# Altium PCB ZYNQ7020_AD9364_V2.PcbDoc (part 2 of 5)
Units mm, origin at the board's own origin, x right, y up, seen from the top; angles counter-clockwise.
Board outline 88.95 x 91.52 mm, 4 copper layers (Top Layer, Layer 1, Layer 2, Bottom Layer), stack 0.603 mm thick; 285 components, 278 nets, 1497 pads, 1247 vias.
Unrouted connection lines stored in the file: 367.
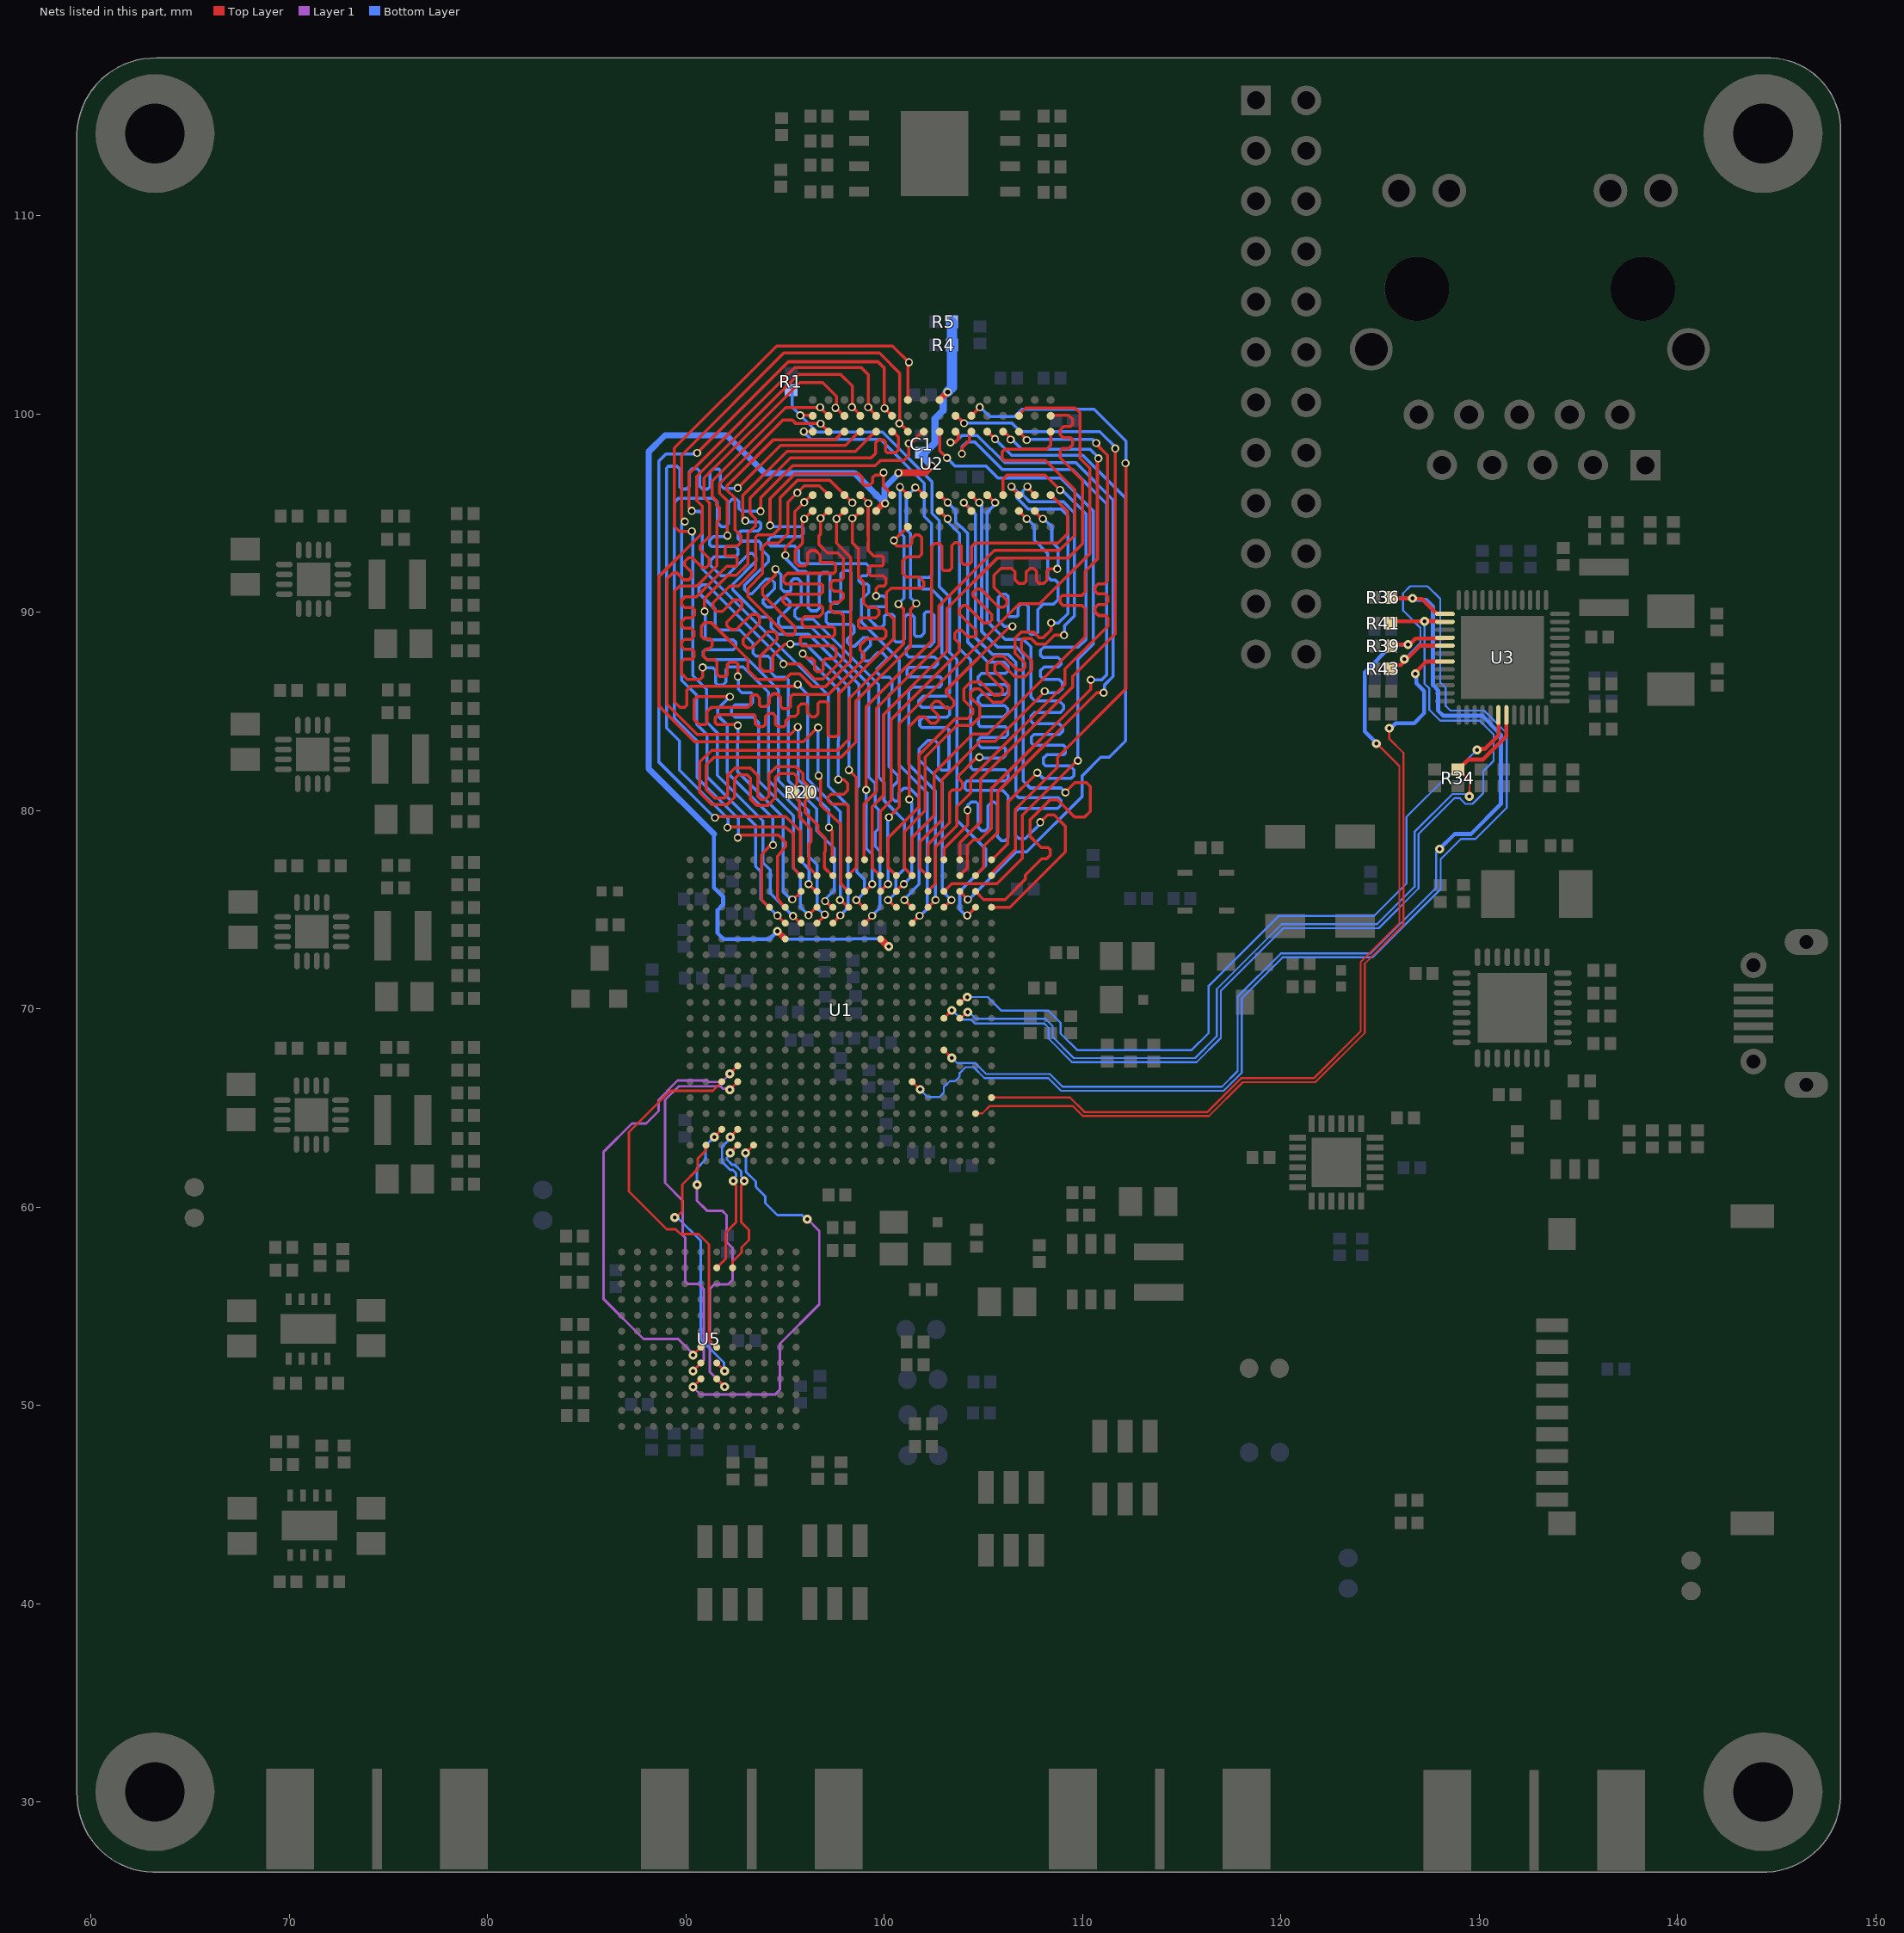
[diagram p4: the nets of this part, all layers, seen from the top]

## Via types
v1: diameter 0.45, hole 0.2, Top Layer to Bottom Layer, tented both sides, 995 vias
v2: diameter 0.406, hole 0.254, Top Layer to Bottom Layer, tented both sides, 118 vias
v3: diameter 1, hole 0.5, Top Layer to Bottom Layer, 116 vias
v4: diameter 0.5, hole 0.3, Top Layer to Bottom Layer, tented both sides, 16 vias
v5: diameter 0.406, hole 0.254, Top Layer to Bottom Layer, 2 vias

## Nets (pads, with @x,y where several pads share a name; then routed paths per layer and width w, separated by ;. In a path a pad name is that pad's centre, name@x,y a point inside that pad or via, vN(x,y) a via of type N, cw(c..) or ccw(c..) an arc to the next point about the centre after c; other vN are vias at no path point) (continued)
CTRL_OUT4: U1.U14 U5.F6 | length 22.7
  Top Layer w0.127: v1(90.354,52.536) U5.F6@90.754,52.934 ; v1@92.217,66.723 U1.U14@92.61,67.116
  Layer 1 w0.102: 91.053,66.389 91.135,66.307 91.805,66.307 v1(92.217,66.718)
  Layer 1 w0.127: v1(90.354,52.536) 90.354,52.597 89.611,53.34 87.859,53.34 85.852,55.347 85.852,62.789 87.274,64.211 87.986,64.211 88.621,64.846 88.621,65.405 89.052,65.837 89.052,65.862 89.579,66.389 91.053,66.389
CTRL_OUT5: U1.U15 U5.F5 | length 19.8
  Top Layer w0.127: v1(90.354,51.734) U5.F5@90.754,52.134 ; v1@92.217,65.923 U1.U15@92.61,66.316
  Layer 1 w0.127: v1(90.354,51.734) 90.907,52.287 90.907,55.855 90.637,56.124 90.053,56.124 89.967,56.21 89.967,58.455 89.842,58.58 89.842,60.323 88.951,61.214 88.951,65.405 89.637,66.091 91.749,66.091 91.876,65.964 92.171,65.964 v1(92.217,65.918)
CTRL_OUT6: U1.T19 U5.F4 | length 21
  Top Layer w0.127: v1(90.354,50.918) 90.354,50.934 U5.F4@90.754,51.334 ; v1(93.006,62.732) 93.013,62.732 93.411,63.129 U1.T19@93.423,63.129
  Layer 1 w0.127: v1(90.354,50.918) v1@90.358,50.914 ; v1@90.358,50.957 v1@90.358,50.914 ; v1(96.123,59.394) 96.723,58.794 96.723,55.093 94.742,53.111 94.742,52.682 94.744,52.68 94.744,50.794 94.489,50.539 93.996,50.539 93.991,50.544 90.728,50.544 v1@90.358,50.914
  Bottom Layer w0.127: v1(90.354,50.918) v1@90.411,50.861 ; v1(93.006,62.732) 93.03,62.707 93.03,61.776 93.521,61.285 93.521,61.02 93.599,60.942 93.599,60.935 93.998,60.535 93.998,60.205 94.615,59.588 95.86,59.588 96.054,59.394 v1(96.123,59.394)
CTRL_OUT7: U1.V18 U5.G4 | length 16.2
  Top Layer w0.127: v1@91.43,63.536 U1.V18@91.823,63.929 ; U5.G4@91.554,51.334 v1(91.954,50.934)
  Layer 1 w0.127: v1@90.553,60.898 90.553,60.323 91.059,59.817 91.821,59.817 92.05,59.588 92.05,58.235 92.344,57.94 92.344,56.32 92.133,56.109 91.44,56.109 91.211,55.88 91.211,51.677 v1(91.954,50.934)
  Bottom Layer w0.127: v1(90.56,61.122) 90.56,61.96 90.991,62.39 90.991,63.092 v1(91.43,63.532)
DATA_CLK_N: U1.U19 U5.H11 | length 7.4
  Top Layer w0.127: v1@92.23,62.736 U1.U19@92.623,63.129 ; U5.H11@92.354,56.934 92.354,57.249 92.811,57.706 92.811,57.965 93.176,58.33 93.176,58.843 92.786,59.233 92.786,61.08 92.939,61.232 v1(92.939,61.316)
  Bottom Layer w0.127: v1(92.23,62.732) 92.23,62.652 92.074,62.496 92.074,62.39 92.342,62.122 92.475,62.122 92.786,61.811 92.786,61.551 92.939,61.399 v1(92.939,61.316)
DATA_CLK_P: U1.U18 U5.G11 | length 8.2
  Top Layer w0.127: U5.G11@91.554,56.934 92.011,57.391 92.011,58.712 92.532,59.233 92.532,61.08 92.38,61.232 v1(92.38,61.316) ; v1@92.23,63.536 U1.U18@92.623,63.929
  Bottom Layer w0.127: v1(92.23,63.532) 92.23,63.454 91.82,63.044 91.82,62.285 92.237,61.868 92.369,61.868 92.532,61.706 92.532,61.551 92.38,61.399 v1(92.38,61.316)
DDR3_A0: U1.N2 U2.N3 | length 40.5
  Top Layer w0.152: v2(92.093,79.142) 92.118,79.167 95.018,79.167 95.418,78.833 95.418,77.106 U1.N2@95.771,76.719 ; v2(92.615,96.266) 94.765,98.416 98.04,98.416 98.79,99.166 U2.N3@98.74,99.166
  Bottom Layer w0.152: v2@92.118,79.217 92.118,79.592 89.668,82.042 89.668,83.513 89.015,84.166 89.015,97.266 89.115,97.366 89.54,97.366 89.69,97.216 89.69,96.316 89.79,96.216 90.015,96.216 90.165,96.366 90.165,97.091 90.315,97.241 90.565,97.241 90.69,97.116 90.69,96.366 90.84,96.216 91.09,96.216 91.215,96.341 91.215,97.091 91.34,97.216 91.665,97.216 91.74,97.141 91.74,96.416 91.915,96.241 v2@92.565,96.241
DDR3_A1: U1.K2 U2.P7 | length 39.7
  Top Layer w0.152: v2(95.265,88.401) 94.99,88.401 94.39,87.801 94.39,87.101 94.315,87.026 93.915,87.026 93.74,87.201 93.74,87.776 94.59,88.626 94.59,88.876 94.44,89.026 94.14,89.026 93.315,88.201 93.09,88.201 92.89,88.401 92.89,88.626 93.715,89.451 93.715,89.751 93.565,89.901 93.315,89.901 92.54,89.126 92.265,89.126 92.065,89.326 92.065,89.501 92.815,90.251 92.815,90.501 92.69,90.626 92.415,90.626 91.84,90.051 91.54,90.051 91.365,90.226 91.365,90.476 92.215,91.326 92.64,91.326 93.515,92.201 93.515,93.801 93.615,93.901 94.39,93.901 94.74,94.251 94.74,95.776 95.615,96.651 97.265,96.651 v2(98.39,95.526) ; U1.K2@98.182,76.719 98.593,77.129 98.593,81.667 v2(98.218,82.042)
  Bottom Layer w0.152: v2(95.265,88.401) 96.04,88.401 98.215,86.226 98.215,84.67 98.218,84.667 v2(98.218,82.042) ; v2(98.39,95.526) v2@98.39,95.551
DDR3_A2: U1.M3 U2.P3 | length 40.6
  Top Layer w0.152: v2@90.84,87.241 90.84,86.741 90.715,86.616 90.065,86.616 89.79,86.891 89.79,87.516 89.915,87.641 90.315,87.641 90.415,87.741 90.415,88.016 90.29,88.141 89.915,88.141 89.79,88.266 89.79,88.516 89.915,88.641 90.265,88.641 90.415,88.791 90.415,89.041 90.265,89.191 89.915,89.191 89.79,89.316 89.79,89.541 89.965,89.716 90.29,89.716 90.44,89.866 90.44,90.116 90.315,90.241 89.94,90.241 89.79,90.391 89.79,90.616 89.965,90.791 90.54,90.791 92.065,92.316 92.515,92.316 92.59,92.391 92.59,92.716 92.465,92.841 92.04,92.841 91.965,92.916 91.965,93.241 92.065,93.341 92.59,93.341 92.765,93.516 92.765,93.866 92.465,94.166 92.465,95.766 92.065,96.166 92.065,96.366 94.39,98.691 97.515,98.691 97.99,99.166 U2.P3@97.965,99.166 ; v2(96.19,76.287) 96.562,75.915 U1.M3@96.571,75.915
  Bottom Layer w0.152: v2@90.965,87.191 91.365,87.191 91.49,87.066 91.49,86.441 91.59,86.341 91.865,86.341 92.015,86.491 92.015,87.116 92.14,87.241 92.89,87.241 94.165,85.966 94.165,84.813 94.165,84.812 94.165,81.512 95.79,79.887 95.79,77.462 96.215,77.037 v2@96.215,76.312
  other v2: 90.84,87.216
DDR3_A3: U1.K3 U2.N2 | length 42.5
  Top Layer w0.152: v2(96.665,84.188) 96.64,84.188 95.915,83.463 90.44,83.463 88.64,85.263 88.64,91.813 90.815,93.988 90.815,95.363 90.54,95.638 90.54,96.863 95.665,101.988 97.815,101.988 98.39,101.413 v2@98.39,100.338 ; v2(96.69,81.762) 96.79,81.662 96.79,80.287 97.803,79.31 97.803,76.339 U1.K3@98.179,75.915 ; v2(98.368,100.341) 98.387,100.341 v2@98.39,100.338 ; U2.N2@98.79,99.963 98.415,100.338 v2@98.39,100.338
  Bottom Layer w0.152: v2(96.665,84.188) 96.665,81.786 v2(96.69,81.762) ; v2@98.34,100.368 v2(98.368,100.341) v2@98.39,100.364
DDR3_A4: U1.M4 U2.P8 | length 40.3
  Top Layer w0.152: v2(92.615,86.763) 92.615,87.388 92.515,87.488 92.215,87.488 92.09,87.363 92.09,86.863 91.99,86.763 91.69,86.763 91.565,86.888 91.565,87.488 91.44,87.613 91.04,87.613 90.89,87.763 90.89,88.013 91.04,88.163 91.165,88.163 91.315,88.313 91.315,88.563 91.215,88.663 90.915,88.663 90.79,88.788 90.79,89.313 90.965,89.488 91.265,89.488 93.115,87.638 93.115,87.088 93.59,86.613 94.99,86.613 95.265,86.888 95.74,86.888 96.39,86.238 97.015,86.238 98.315,87.538 98.315,92.763 97.59,93.488 v2(97.59,94.713) ; v2@96.164,74.683 96.164,74.705 v2(96.181,74.722) U1.M4@96.571,75.112 ; v2@97.559,94.682 97.965,95.088 U2.P8@97.99,95.088
  Bottom Layer w0.152: v2@92.64,86.713 92.64,86.113 92.815,85.938 93.29,85.938 93.365,85.863 93.365,85.438 93.265,85.338 92.465,85.338 92.29,85.163 92.29,84.888 92.465,84.713 93.39,84.713 93.659,84.444 93.659,81.489 95.414,79.733 95.414,77.083 95.771,76.727 95.771,76.41 95.771,75.133 v2(96.181,74.722)
DDR3_A5: U1.L1 U2.P2 | length 40.1
  Top Layer w0.152: v2(95.64,84.213) 95.265,83.838 90.565,83.838 89.04,85.363 89.04,91.688 89.34,91.988 89.54,91.988 89.89,91.638 90.14,91.638 90.29,91.788 90.29,92.013 89.94,92.363 89.94,92.563 90.14,92.763 90.315,92.763 90.815,92.263 91.015,92.263 91.165,92.413 91.165,92.713 90.715,93.163 90.715,93.363 91.19,93.838 91.19,95.513 90.915,95.788 90.915,96.763 95.74,101.588 96.89,101.588 97.59,100.888 v2@97.59,100.313 ; v2(97.212,79.141) 97.372,78.981 U1.L1@97.372,77.541 ; v2@97.565,100.313 97.915,99.963 U2.P2@97.99,99.963
  Bottom Layer w0.152: v2(95.64,84.213) 95.665,84.188 95.665,82.57 95.662,82.566 95.662,81.566 97.212,80.016 v2(97.212,79.141)
  other v2: 97.54,100.313
DDR3_A6: U1.L4 U2.R8 | length 40.9
  Top Layer w0.152: v2(94.915,87.388) 95.74,87.388 96.49,86.638 96.915,86.638 97.94,87.663 97.94,89.838 97.79,89.988 97.44,89.988 97.29,90.138 97.29,90.338 97.465,90.513 97.74,90.513 97.94,90.713 97.94,90.938 97.815,91.063 97.465,91.063 97.315,91.213 97.315,91.488 97.44,91.613 97.815,91.613 97.94,91.738 97.94,92.713 97.665,92.988 97.14,92.988 96.711,93.418 96.711,93.86 96.79,93.939 v2(96.79,94.738) 97.14,95.088 U2.R8@97.19,95.088 ; v2@96.989,75.483 97.361,75.112 U1.L4@97.375,75.112
  Bottom Layer w0.152: v2@94.965,87.313 94.965,87.488 91.065,91.388 90.815,91.388 90.64,91.213 90.64,90.988 91.465,90.163 91.465,89.288 91.64,89.113 92.715,89.113 93.39,88.438 93.39,87.938 93.54,87.788 94.14,87.788 94.29,87.638 94.29,86.963 94.54,86.713 95.04,86.713 95.165,86.588 95.165,85.813 ; 95.164,85.813 95.164,81.508 96.589,80.083 96.589,78.983 97.489,78.083 97.489,75.983 v2@96.989,75.483
  other v2: 97.014,75.433
DDR3_A7: U1.K4 U2.R2 | length 39.8
  Top Layer w0.152: v2(95.64,86.363) 95.54,86.263 90.24,86.263 90.04,86.063 90.04,85.313 89.94,85.213 89.69,85.213 89.415,85.488 89.415,91.063 89.665,91.313 90.54,91.313 91.565,92.338 91.565,94.563 91.69,94.688 91.69,95.263 91.54,95.413 91.54,95.638 91.315,95.863 91.315,96.613 95.032,100.33 96.215,100.33 96.222,100.324 96.751,100.324 v2(96.765,100.338) 97.14,99.963 U2.R2@97.19,99.963 ; v2(97.764,75.483) 97.808,75.483 U1.K4@98.179,75.112
  Bottom Layer w0.152: v2@95.715,86.288 96.038,85.965 96.139,85.864 96.139,83.734 96.142,83.731 96.142,83.335 96.139,83.332 96.139,82.734 96.142,82.731 96.142,82.335 96.139,82.332 96.139,81.583 97.789,79.933 97.789,75.508 v2(97.764,75.483)
DDR3_A8: U1.K1 U2.T8 | length 40.3
  Top Layer w0.152: v2@95.915,87.888 96.115,87.688 96.34,87.688 96.49,87.538 96.49,87.113 96.59,87.013 96.84,87.013 96.915,87.088 96.915,87.538 97.04,87.663 97.465,87.663 97.565,87.763 97.565,88.163 97.415,88.313 95.865,88.313 95.765,88.413 95.765,88.688 95.84,88.763 97.39,88.763 97.515,88.888 97.515,89.163 97.415,89.263 95.99,89.263 95.865,89.388 95.865,89.663 95.99,89.788 96.715,89.788 96.89,89.963 96.89,90.238 96.765,90.363 95.065,90.363 95.015,90.413 94.89,90.538 94.89,90.713 95.09,90.913 96.79,90.913 96.89,91.013 96.89,91.363 96.815,91.438 95.04,91.438 94.915,91.563 94.915,91.763 95.115,91.963 97.44,91.963 97.54,92.063 97.54,92.388 97.415,92.513 96.815,92.513 96.765,92.563 96.765,92.888 96.54,93.113 96.29,93.113 96.14,92.963 96.14,92.463 96.015,92.338 95.69,92.338 95.515,92.513 95.515,93.113 95.886,93.484 95.886,94.584 95.915,94.613 95.915,94.663 v2(95.965,94.713) 96.34,95.088 U2.T8@96.39,95.088 ; v2(97.687,81.566) 97.962,81.566 98.162,81.366 98.162,81.016 97.962,80.816 97.312,80.816 97.162,80.666 97.162,80.491 97.337,80.316 98.062,80.316 98.176,80.202 U1.K1@98.176,77.541
  Bottom Layer w0.152: v2@95.93,87.873 97.69,86.113 97.69,83.538 97.687,83.535 v2(97.687,81.566)
  other v2: 95.89,87.913
DDR3_A9: U1.J4 U2.R3 | length 40.2
  Top Layer w0.152: v2(92.09,93.866) 92.09,95.616 91.69,96.016 91.69,96.491 94.89,99.691 95.365,99.691 95.54,99.516 v2(96.79,99.516) 97.14,99.166 U2.R3@97.19,99.166 ; v2@98.614,75.458 98.961,75.112 U1.J4@98.983,75.112
  Bottom Layer w0.152: v2@92.065,93.816 91.39,93.816 91.19,93.616 91.19,93.416 91.29,93.316 92.49,93.316 92.615,93.191 92.615,92.916 92.49,92.791 91.415,92.791 91.24,92.616 91.24,92.366 91.765,91.841 92.065,91.841 93.19,92.966 93.34,92.966 93.54,92.766 93.54,92.591 92.365,91.416 92.365,91.141 93.74,89.766 94.165,89.766 94.29,89.641 94.29,89.241 94.64,88.891 96.19,88.891 98.715,86.366 98.715,84.484 98.714,84.483 98.714,81.233 98.614,81.133 98.614,76.908 99.009,76.513 99.009,75.878 v2@98.564,75.433 ; v2@96.715,99.516 v2@96.715,99.616
  other v2: 98.589,75.483
DDR3_A10: U1.F5 U2.L7 | length 40.2
  Top Layer w0.152: v2(94.24,94.376) 94.24,95.726 95.49,96.976 98.715,96.976 98.89,96.801 98.89,96.526 99.015,96.401 99.265,96.401 99.415,96.551 99.415,96.801 99.54,96.926 99.84,96.926 v2(99.965,97.051) 99.965,96.351 U2.L7@100.39,95.926 ; U1.F5@101.392,74.322 101.762,74.691 v2(101.787,74.691)
  Bottom Layer w0.152: v2@94.365,94.351 94.39,94.326 95.815,94.326 95.915,94.226 95.915,93.976 95.765,93.826 94.315,93.826 94.165,93.676 94.165,93.451 94.265,93.351 95.465,93.351 95.69,93.126 95.69,92.576 95.815,92.451 99.09,92.451 99.265,92.276 99.265,92.001 99.115,91.851 98.89,91.851 98.715,91.676 98.715,91.576 98.865,91.426 99.14,91.426 99.215,91.351 99.215,91.001 98.84,90.626 98.84,89.526 100.765,87.601 100.765,83.551 100.762,83.548 100.762,82.291 102.162,80.891 102.162,75.041 v2@101.787,74.666 ; v2@99.89,97.076 v2@99.89,97.101
DDR3_A11: U1.G4 U2.R7 | length 38.6
  Top Layer w0.152: v2(94.515,92.176) 94.515,91.876 93.865,91.226 93.865,90.901 95.515,89.251 95.515,88.976 95.39,88.851 95.065,88.851 93.115,90.801 93.115,91.201 93.865,91.951 93.865,93.301 94.065,93.501 94.665,93.501 95.14,93.976 95.14,95.551 v2(95.615,96.026) 95.965,96.376 96.728,96.376 U2.R7@97.194,95.91 ; v2(100.189,75.483) 100.561,75.112 U1.G4@100.591,75.112
  Bottom Layer w0.152: v2(94.515,92.176) 94.79,91.901 94.79,91.201 94.94,91.051 95.24,91.051 95.29,91.101 95.29,91.551 95.44,91.701 95.64,91.701 95.815,91.526 95.815,90.426 95.49,90.101 95.49,89.801 95.64,89.651 96.415,89.651 99.715,86.351 99.715,81.683 99.989,81.408 99.989,80.508 101.014,79.483 101.014,77.058 100.589,76.633 100.589,75.858 100.214,75.483 v2(100.189,75.483)
DDR3_A12: U1.E4 U2.N7 | length 41.2
  Top Layer w0.152: U2.N7@98.79,95.926 v2@99.19,95.526 ; v2(99.19,95.501) 99.187,95.498 99.187,93.911 99.205,93.893 99.205,93.559 99.187,93.541 99.187,93.129 99.465,92.851 99.865,92.851 99.965,92.751 99.965,92.426 99.89,92.351 99.315,92.351 99.19,92.226 99.19,91.976 99.315,91.851 99.94,91.851 100.09,91.701 100.09,91.426 99.99,91.326 99.715,91.326 99.59,91.201 v2(99.59,90.826) ; U1.E4@102.199,75.112 102.218,75.112 v2(102.589,75.483)
  Bottom Layer w0.152: v2(99.19,95.501) v2@99.19,95.551 ; v2@99.665,90.826 99.965,90.826 100.115,90.676 100.115,90.351 100.04,90.276 99.315,90.276 99.215,90.176 99.215,89.676 99.64,89.251 99.865,89.251 99.99,89.376 99.99,89.776 100.115,89.901 100.39,89.901 100.49,89.801 100.49,88.601 100.59,88.501 100.865,88.501 101.015,88.651 101.015,89.751 101.165,89.901 101.365,89.901 101.515,89.751 101.515,88.876 101.615,88.776 101.84,88.776 102.015,88.951 102.015,89.926 102.115,90.026 102.34,90.026 102.515,89.851 102.515,88.501 102.29,88.276 101.24,88.276 101.115,88.151 101.115,87.876 101.24,87.751 102.54,87.751 102.69,87.601 102.69,87.376 102.54,87.226 101.24,87.226 101.14,87.126 101.14,86.851 101.24,86.751 102.815,86.751 102.89,86.676 102.89,86.326 102.79,86.226 101.44,86.226 101.24,86.026 101.24,82.333 102.589,80.983 v2(102.589,75.483)
DDR3_A13: U1.D4 U2.T3 | length 40.9
  Top Layer w0.152: v2@95.89,99.116 v2(95.94,99.116) 96.34,99.116 U2.T3@96.39,99.166 ; U1.D4@103.003,75.112 103.018,75.112 v2(103.389,75.483)
  Bottom Layer w0.152: v2@95.928,99.103 96.315,98.716 99.815,98.716 102.015,96.516 102.015,94.841 102.39,94.466 102.39,91.866 102.29,91.766 101.84,91.766 101.765,91.691 101.765,91.341 101.94,91.166 102.39,91.166 102.915,90.641 102.915,87.916 103.29,87.541 103.29,85.916 103.14,85.766 101.965,85.766 101.74,85.541 101.74,85.366 101.89,85.216 103.19,85.216 103.29,85.116 103.29,84.841 103.165,84.716 101.965,84.716 101.79,84.541 101.79,84.291 101.89,84.191 103.14,84.191 103.265,84.066 103.265,82.091 103.215,82.041 102.89,82.041 102.74,82.191 102.74,83.366 102.565,83.541 102.203,83.541 101.764,83.102 101.764,82.558 102.939,81.383 102.939,75.933 v2(103.389,75.483)
DDR3_A14: U1.F4 U2.T7 | length 40.4
  Top Layer w0.152: v2(95.015,92.876) 95.015,93.251 95.49,93.726 95.49,95.076 v2(95.965,95.551) 96.34,95.926 U2.T7@96.39,95.926 ; v2(101.014,75.483) 101.024,75.483 U1.F4@101.395,75.112
  Bottom Layer w0.152: v2@95.04,92.826 95.04,92.701 95.69,92.051 96.04,92.051 96.165,91.926 96.165,90.226 96.315,90.076 96.59,90.076 96.715,90.201 96.715,91.826 96.915,92.026 97.14,92.026 97.265,91.901 97.265,90.551 97.365,90.451 97.665,90.451 97.815,90.601 97.815,91.951 97.965,92.101 98.215,92.101 98.34,91.976 98.34,90.126 98.24,90.026 97.165,90.026 97.065,89.926 97.065,89.526 97.19,89.401 98.34,89.401 98.49,89.251 98.49,89.001 98.14,88.651 98.14,88.476 98.34,88.276 98.49,88.276 98.94,88.726 99.165,88.726 99.315,88.576 99.315,88.351 98.89,87.926 98.89,87.676 99.015,87.551 99.265,87.551 99.665,87.951 99.915,87.951 100.115,87.751 100.115,87.626 99.64,87.151 99.64,86.951 99.865,86.726 100.265,86.726 100.39,86.601 100.39,85.976 100.24,85.826 100.24,84.809 100.239,82.208 100.689,81.758 100.689,81.483 100.389,81.183 100.389,80.633 100.539,80.483 100.689,80.483 100.739,80.533 100.739,80.883 100.989,81.133 101.289,81.133 101.764,80.658 101.764,76.283 v2@101.039,75.558 ; v2@95.94,95.526 v2(95.965,95.551)
DDR3_BA0: U1.L5 U2.M2 | length 40.2
  Top Layer w0.152: v2(90.29,95.113) 90.14,95.263 90.14,96.988 95.49,102.338 98.84,102.338 99.19,101.988 v2(99.19,100.338) 99.565,99.963 U2.M2@99.59,99.963 ; U1.L5@97.373,74.322 97.392,74.322 v2(97.787,74.716)
  Bottom Layer w0.152: v2@90.24,95.088 90.69,95.088 90.815,94.963 90.815,92.188 97.165,85.838 97.165,85.813 97.187,85.791 97.187,81.241 98.169,80.26 98.169,75.098 v2(97.787,74.716)
DDR3_BA1: U1.R4 U2.N8 | length 39.7
  Top Layer w0.152: v2(92.215,85.738) 90.565,85.738 90.415,85.588 90.415,84.588 90.665,84.338 90.99,84.338 91.065,84.413 91.065,84.988 91.29,85.213 93.115,85.213 93.265,85.363 93.265,85.738 93.365,85.838 93.565,85.838 93.715,85.688 93.715,85.313 93.79,85.238 94.04,85.238 94.215,85.413 94.215,85.713 94.39,85.888 94.59,85.888 94.765,85.713 94.765,85.263 94.89,85.138 95.165,85.138 95.265,85.238 95.265,85.738 95.39,85.863 97.19,85.863 98.99,87.663 98.99,87.888 98.79,88.088 98.79,88.338 99.115,88.663 99.965,88.663 100.09,88.788 100.09,89.063 99.965,89.188 98.815,89.188 98.69,89.313 98.69,89.563 98.84,89.713 99.565,89.713 99.74,89.888 99.74,90.088 99.59,90.238 99.19,90.238 98.965,90.463 98.965,91.538 98.69,91.813 98.69,93.213 98.4,93.504 98.4,94.729 v2(98.39,94.738) 98.44,94.738 U2.N8@98.79,95.088 ; U1.R4@94.159,75.112 93.815,75.497 93.815,77.757 94.264,78.258 v2(94.389,78.258)
  Bottom Layer w0.152: v2(92.215,85.738) 91.614,85.138 91.614,84.783 92.089,84.308 92.089,81.908 94.389,79.608 v2(94.389,78.258) ; v2@98.365,94.738 v2(98.39,94.738)
DDR3_BA2: U1.J5 U2.M3 | length 41.1
  Top Layer w0.152: v2(92.99,94.616) 92.865,94.741 92.865,95.891 95.09,98.116 98.54,98.116 99.59,99.166 U2.M3@99.565,99.166 ; U1.J5@98.981,74.322 99.017,74.322 v2(99.387,74.691)
  Bottom Layer w0.152: v2@93.09,94.566 93.69,94.566 93.765,94.491 93.765,94.241 93.615,94.091 92.765,94.091 92.615,93.941 92.615,93.741 92.765,93.591 93.665,93.591 93.765,93.491 93.765,93.216 94.165,92.816 94.165,92.566 92.94,91.341 92.94,91.166 93.165,90.941 93.315,90.941 94.04,91.666 94.29,91.666 94.465,91.491 94.465,91.191 93.89,90.616 93.89,90.466 94.09,90.266 94.34,90.266 94.79,90.716 95.065,90.716 95.24,90.541 95.24,90.266 94.665,89.691 94.665,89.391 94.815,89.241 96.34,89.241 99.215,86.366 99.215,85.841 99.212,85.837 99.212,81.691 99.537,81.366 99.537,80.216 99.712,80.041 99.712,79.091 99.537,78.916 99.537,78.191 99.787,77.941 99.787,75.091 v2@99.337,74.641
DDR3_CAS: U1.P5 U2.K3 | length 42.4
  Top Layer w0.152: v2(89.937,94.575) 89.787,94.725 89.787,97.925 94.937,103.075 99.762,103.075 100.787,102.05 100.787,99.55 101.162,99.175 U2.K3@101.187,99.175 ; v2(94.616,74.701) 94.616,74.68 U1.P5@94.964,74.331
  Bottom Layer w0.152: v2@89.862,94.525 89.787,94.45 89.787,86.575 90.541,85.821 90.541,84.351 91.066,83.826 91.066,81.701 93.516,79.251 93.516,77.176 93.766,76.926 93.766,75.526 94.591,74.701 v2@94.591,74.676
  other v2: 100.762,99.525
DDR3_CK_N: R20.2 U1.M2 U2.K7 | length 38.9
  Top Layer w0.152: R20.2@95.243,81.167 95.418,81.167 95.593,81.342 95.593,81.717 95.443,81.867 94.718,81.867 94.518,81.667 94.518,80.642 94.143,80.267 93.568,80.267 93.243,80.592 93.243,81.642 93.093,81.792 92.643,81.792 92.443,81.592 92.443,80.667 92.068,80.292 91.318,80.292 90.693,80.917 90.693,82.442 91.293,83.042 97.668,83.042 98.243,83.617 98.243,85.667 100.968,88.392 100.968,90.167 v2(100.718,90.417) ; R20.2@95.318,81.067 95.318,80.892 95.718,80.492 95.718,79.667 96.318,79.067 96.318,78.467 96.206,78.3 96.206,77.157 U1.M2@96.574,76.719 ; v2@100.768,96.317 v2(100.793,96.317) U2.K7@101.193,95.917
  Bottom Layer w0.152: v2@100.693,90.417 100.993,90.717 100.993,93.817 100.793,94.017 v2(100.793,96.317)
DDR3_CK_P: R20.1 U1.L2 U2.J7 | length 39.3
  Top Layer w0.152: R20.1@96.243,81.117 96.243,80.692 96.018,80.467 96.018,79.892 96.668,79.242 96.668,78.955 97.024,78.598 97.024,77.935 96.993,77.903 96.993,77.104 U1.L2@97.378,76.719 ; R20.1@96.243,81.167 95.893,81.517 95.893,81.867 95.543,82.217 94.568,82.217 94.193,81.842 94.193,80.742 94.018,80.567 93.768,80.567 93.618,80.717 93.618,81.767 93.243,82.142 92.468,82.142 92.093,81.767 92.093,80.792 91.918,80.617 91.468,80.617 91.018,81.067 91.018,82.292 91.418,82.692 97.818,82.692 98.568,83.442 98.568,85.517 101.318,88.267 101.318,90.142 v2(101.618,90.442) ; v2@101.593,96.342 101.593,96.317 U2.J7@101.993,95.917
  Bottom Layer w0.152: v2@101.568,96.267 101.118,95.817 101.118,94.167 101.318,93.967 101.318,90.742 v2(101.618,90.442)
  other v2: 101.568,96.292
DDR3_CKE: U1.N3 U2.K9 | length 40.7
  Top Layer w0.152: v2@92.615,84.346 91.565,84.346 91.465,84.446 91.465,84.671 91.64,84.846 93.415,84.846 93.49,84.771 93.49,84.371 93.64,84.221 93.89,84.221 94.015,84.346 94.015,84.746 94.165,84.896 94.39,84.896 94.515,84.771 94.515,84.346 94.64,84.221 94.94,84.221 95.04,84.321 95.04,84.521 95.265,84.746 95.515,84.746 95.665,84.896 95.665,85.221 95.815,85.371 96.04,85.371 96.115,85.296 96.115,84.946 96.34,84.721 96.515,84.721 96.665,84.871 96.665,85.396 96.765,85.496 97.065,85.496 97.165,85.396 97.165,83.846 97.29,83.721 97.565,83.721 97.69,83.846 97.69,85.871 100.49,88.671 100.49,89.646 100.115,90.021 100.115,90.996 100.34,91.221 101.89,91.221 101.99,91.321 101.99,91.546 101.765,91.771 101.115,91.771 100.94,91.946 100.94,92.596 101.14,92.796 101.765,92.796 101.89,92.921 101.89,93.771 101.765,93.896 101.565,93.896 101.39,93.721 101.39,93.471 101.265,93.346 100.64,93.346 100.49,93.496 v2(100.49,93.621) U2.K9@101.19,94.321 ; v5@95.386,75.478 U1.N3@95.764,75.856
  Bottom Layer w0.152: v2@92.615,84.246 92.615,83.521 92.611,83.517 92.611,81.953 94.911,79.653 94.911,75.903 v5@95.299,75.516
  other v2: 92.615,84.296
  other v5: 95.361,75.518
DDR3_CS: U1.N1 U2.L2 | length 41.2
  Top Layer w0.152: v2(90.565,98.038) 95.165,102.638 99.684,102.638 100.009,102.313 100.009,100.294 100.34,99.963 U2.L2@100.39,99.963 ; v2(91.462,79.641) 91.512,79.691 95.037,79.691 95.764,78.964 U1.N1@95.764,77.541
  Bottom Layer w0.152: v2(90.565,98.038) 90.515,97.988 88.99,97.988 88.64,97.638 88.64,82.438 91.337,79.741 v2@91.362,79.741
  other v2: 100.015,100.288
DDR3_DM0: U1.A1 U2.E7 | length 32.8
  Top Layer w0.152: U2.E7@105.194,95.91 105.569,95.535 v2(105.594,95.535) ; U1.A1@105.419,77.51 106.219,78.31 106.219,80.41 v2(107.719,81.91)
  Bottom Layer w0.152: v2@105.569,95.435 105.194,95.06 105.194,89.535 106.094,88.635 107.019,88.635 107.394,88.26 107.394,85.735 107.594,85.535 108.819,85.535 109.044,85.31 109.044,85.11 108.869,84.935 107.569,84.935 107.394,84.76 107.394,84.51 107.519,84.385 108.819,84.385 108.994,84.21 108.994,83.985 108.844,83.835 107.544,83.835 107.419,83.71 107.419,83.41 107.544,83.285 109.044,83.285 109.144,83.185 109.144,82.91 109.044,82.81 108.194,82.81 108.019,82.635 108.019,82.385 108.144,82.26 109.369,82.26 109.569,82.06 109.569,81.76 109.444,81.635 107.994,81.635 v2(107.719,81.91)
DDR3_DM1: U1.F1 U2.D3 | length 32.1
  Top Layer w0.152: U1.F1@101.406,77.512 101.406,78.643 102.526,79.762 102.526,81.912 104.476,83.862 105.226,83.862 110.126,88.762 110.126,90.187 109.976,90.337 109.026,90.337 108.876,90.487 108.876,90.737 108.976,90.837 109.951,90.837 110.126,91.012 110.126,92.062 110.751,92.687 v2@110.751,97.737 ; U2.D3@106.001,99.162 106.376,98.787 v2(106.376,98.712)
  Bottom Layer w0.152: v2(106.376,98.712) 106.451,98.712 106.951,98.212 110.401,98.212 v2@110.826,97.787
  other v2: 110.801,97.762
DDR3_DQ0: U1.C3 U2.E3 | length 33
  Top Layer w0.152: U1.C3@103.807,75.915 104.209,75.512 v2(104.215,75.512) ; U2.E3@105.19,99.162 105.19,99.137 v2(105.59,98.737)
  Bottom Layer w0.152: v2@104.29,75.562 104.315,75.562 106.665,77.912 107.19,77.912 109.99,80.712 109.99,81.762 110.915,82.687 111.34,82.687 112.165,83.512 112.165,95.762 110.015,97.912 106.415,97.912 v2(105.59,98.737)
DDR3_DQ1: U1.B3 U2.F7 | length 32.6
  Top Layer w0.152: U2.F7@104.39,95.912 104.765,95.537 v2(104.79,95.537) ; U1.B3@104.611,75.915 105.013,75.512 106.09,75.512 107.115,76.537 107.115,76.737 107.94,77.562 108.19,77.562 108.365,77.737 108.365,78.037 108.265,78.137 107.915,78.137 107.365,78.687 107.365,79.537 108.365,80.537 108.74,80.537 109.615,79.662 110.09,79.662 110.39,79.962 110.39,81.212 110.19,81.412 109.615,81.412 109.14,80.937 v2(109.14,80.912)
  Bottom Layer w0.152: v2(104.79,95.537) 104.915,95.412 104.915,89.037 105.715,88.237 106.665,88.237 107.015,87.887 107.015,81.487 107.365,81.137 108.915,81.137 v2(109.14,80.912)
DDR3_DQ2: U1.A2 U2.F2 | length 33.6
  Top Layer w0.152: U2.F2@104.393,99.967 104.447,99.967 104.818,100.339 v2(104.818,100.342) ; U1.A2@105.418,76.719 105.418,76.842 106.618,78.042 106.618,80.067 108.743,82.192 108.743,82.692 112.201,86.151 112.201,97.484 v2(112.168,97.517)
  Bottom Layer w0.152: v2@104.843,100.342 105.318,99.867 106.568,99.867 106.943,100.242 110.593,100.242 112.193,98.642 v2@112.193,97.592
DDR3_DQ3: U1.A4 U2.F8 | length 32.6
  Top Layer w0.152: v2(104.014,95.533) 104.389,95.158 U2.F8@104.389,95.083 ; U1.A4@105.414,75.112 106.343,75.112 109.139,77.908 109.139,79.208 108.564,79.783 108.239,79.783 v2(107.864,79.408)
  Bottom Layer w0.152: v2@104.089,95.458 104.589,94.958 104.589,88.733 105.439,87.883 106.239,87.883 106.639,87.483 106.639,80.783 106.764,80.658 108.764,80.658 108.914,80.508 108.914,80.283 108.739,80.108 106.789,80.108 106.614,79.933 106.614,78.758 106.789,78.583 107.114,78.583 107.864,79.333 v2(107.864,79.408)
DDR3_DQ4: U1.D3 U2.H3 | length 33.7
  Top Layer w0.152: U2.H3@102.79,99.162 102.79,98.162 v2(103.165,97.787) ; U1.D3@103.003,75.915 103.4,76.312 105.69,76.312 106.965,77.587 106.965,79.762 109.715,82.512 v2(109.765,82.512)
  Bottom Layer w0.152: v2(103.165,97.787) 103.565,97.387 105.115,97.387 105.74,96.762 108.89,96.762 110.54,95.112 110.54,88.387 109.765,87.612 109.765,82.537 v2@109.815,82.487
DDR3_DQ5: U1.D1 U2.H8 | length 32.6
  Top Layer w0.152: U2.H8@102.801,95.087 102.826,95.087 v2(103.201,94.712) ; U1.D1@103.014,77.512 103.014,78.076 104.201,79.262 v2(104.201,80.012)
  Bottom Layer w0.152: v2@103.226,94.762 103.226,94.537 103.801,93.962 103.801,88.162 104.351,87.612 104.351,82.187 104.476,82.062 106.101,82.062 106.251,81.912 106.251,81.612 106.126,81.487 104.176,81.487 104.076,81.387 104.076,81.112 104.176,81.012 105.976,81.012 106.251,80.737 106.251,78.637 106.101,78.487 105.901,78.487 105.701,78.687 105.701,80.287 105.551,80.437 105.426,80.437 105.226,80.237 105.226,79.112 105.101,78.987 104.901,78.987 104.726,79.162 104.726,80.337 104.626,80.437 104.376,80.437 104.201,80.262 v2(104.201,80.012)
DDR3_DQ6: U1.C1 U2.G2 | length 32.9
  Top Layer w0.152: U2.G2@103.601,99.962 v2(104.026,99.537) ; U1.C1@103.818,77.512 103.818,78.379 104.851,79.412 104.851,81.587 109.501,86.237 109.501,86.762 111.651,88.912 v2(111.651,98.262)
  Bottom Layer w0.152: v2(104.026,99.537) 106.451,99.537 106.876,99.112 110.876,99.112 v2@111.751,98.237
DDR3_DQ7: U1.E1 U2.H7 | length 33.8
  Top Layer w0.152: U1.E1@102.21,77.512 102.21,78.297 103.301,79.387 103.301,80.912 103.426,81.037 103.826,81.037 103.951,81.162 103.951,81.412 103.751,81.612 103.751,81.762 104.676,82.687 v2(104.801,82.687) ; U2.H7@102.801,95.912 102.826,95.912 v2(103.201,95.537)
  Bottom Layer w0.152: v2(103.201,95.537) 103.607,95.131 103.607,94.556 103.857,94.306 103.882,94.306 104.201,93.987 104.201,88.512 105.226,87.487 106.051,87.487 106.251,87.287 106.251,87.037 106.126,86.912 104.901,86.912 104.726,86.737 104.726,86.487 104.851,86.362 106.101,86.362 106.251,86.212 106.251,86.012 106.101,85.862 104.901,85.862 104.726,85.687 104.726,85.487 104.926,85.287 106.076,85.287 106.226,85.137 106.226,84.937 106.026,84.737 104.876,84.737 104.751,84.612 104.751,84.337 104.851,84.237 106.101,84.237 106.226,84.112 106.226,83.812 106.101,83.687 104.851,83.687 104.726,83.562 104.726,83.337 104.901,83.162 106.076,83.162 106.126,83.112 106.126,82.787 105.976,82.637 104.851,82.637 v2(104.801,82.687)
DDR3_DQ8: U1.E2 U2.D7 | length 32.7
  Top Layer w0.152: U1.E2@102.202,76.719 102.167,76.719 101.793,77.092 101.793,78.417 102.918,79.542 102.918,81.567 104.843,83.492 105.593,83.492 108.093,85.992 v2(108.093,86.017) ; U2.D7@105.993,95.917 105.993,96.717 106.193,96.917 108.118,96.917 v2(108.868,96.167)
  Bottom Layer w0.152: v2(108.093,86.017) 108.168,85.942 108.768,85.942 108.993,86.167 108.993,86.442 108.818,86.617 108.043,86.617 107.868,86.792 107.868,87.042 108.068,87.242 108.793,87.242 108.918,87.367 108.918,87.567 108.768,87.717 107.993,87.717 107.868,87.842 107.868,88.067 108.043,88.242 109.793,88.242 110.168,88.617 110.168,94.967 109.018,96.117 v2@108.993,96.117
DDR3_DQ9: U1.E3 U2.C3 | length 32.7
  Top Layer w0.152: U1.E3@102.199,75.915 102.59,76.305 102.59,78.162 103.665,79.237 103.665,80.187 104.365,80.887 104.365,81.612 109.115,86.362 109.115,87.137 111.29,89.312 111.29,89.712 111.165,89.837 110.815,89.837 110.64,90.012 110.64,90.237 110.79,90.387 111.14,90.387 111.29,90.537 111.29,90.787 111.14,90.937 110.765,90.937 110.64,91.062 110.64,91.287 110.79,91.437 111.115,91.437 111.265,91.587 111.265,97.912 v2@110.64,98.537 ; U2.C3@106.79,99.162 106.79,99.112 v2@107.19,98.712
  Bottom Layer w0.152: v2@107.19,98.712 110.515,98.712 v2(110.69,98.537)
  other v2: 107.19,98.687
DDR3_DQ10: U1.G3 U2.C8 | length 33.2
  Top Layer w0.152: U1.G3@100.591,75.915 100.963,76.287 v2(100.99,76.287) ; v2@101.29,80.562 v2(101.265,80.562) 101.265,84.237 101.765,84.737 102.015,84.737 102.34,84.412 102.59,84.412 102.74,84.562 102.74,84.787 102.39,85.137 102.39,85.337 102.565,85.512 102.765,85.512 103.115,85.162 103.365,85.162 103.515,85.312 103.515,85.537 103.115,85.937 103.115,86.062 106.34,89.287 v2(106.465,89.287) ; U2.C8@106.79,95.087 106.815,95.087 v2(107.19,94.712)
  Bottom Layer w0.152: v2(100.99,76.287) 101.39,76.687 101.39,80.387 v2@101.315,80.462 ; v2@106.365,89.287 106.065,89.287 105.74,89.612 105.74,90.737 105.915,90.912 106.14,90.912 106.24,90.812 106.24,89.837 106.29,89.787 106.69,89.787 106.74,89.837 106.74,90.262 106.89,90.412 107.14,90.412 107.265,90.287 107.265,89.012 107.39,88.887 107.64,88.887 107.74,88.987 107.74,90.137 108.015,90.412 108.54,90.412 108.765,90.637 108.765,91.487 108.615,91.637 108.39,91.637 108.24,91.787 108.24,92.962 107.565,93.637 107.565,94.362 107.215,94.712 v2(107.19,94.712)
DDR3_DQ11: U1.H3 U2.C2 | length 32.7
  Top Layer w0.152: U1.H3@99.787,75.915 99.792,75.915 v2@100.165,76.287 ; v2(100.24,79.662) 100.765,80.187 100.765,84.387 106.815,90.437 107.84,90.437 110.365,92.962 110.365,97.262 109.865,97.762 109.865,100.062 109.622,100.305 107.132,100.305 U2.C2@106.79,99.962
  Bottom Layer w0.152: v2@100.14,76.237 v2(100.19,76.287) 100.19,77.887 100.183,77.894 100.183,79.606 v2(100.24,79.662)
DDR3_DQ12: U1.J3 U2.A7 | length 32.7
  Top Layer w0.152: U1.J3@99.017,75.915 99.017,75.921 99.383,76.287 v2(99.39,76.287) ; v2(99.09,81.037) 99.09,85.237 102.39,88.537 102.39,93.312 102.54,93.462 102.79,93.462 102.915,93.337 102.915,92.187 102.99,92.112 103.29,92.112 103.415,92.237 103.415,93.362 103.565,93.512 103.715,93.512 103.89,93.337 103.89,92.537 104.015,92.412 104.265,92.412 104.415,92.562 104.415,93.312 104.59,93.487 108.765,93.487 109.24,93.962 109.24,95.087 108.415,95.912 U2.A7@108.39,95.912
  Bottom Layer w0.152: v2@99.09,80.937 99.09,78.087 99.39,77.787 v2@99.39,76.288
DDR3_DQ13: U1.H2 U2.A2 | length 32.6
  Top Layer w0.152: U1.H2@99.79,76.719 99.393,77.116 99.393,80.192 99.968,80.767 99.968,84.842 103.168,88.042 103.168,90.192 105.718,92.742 109.293,92.742 109.993,93.442 109.993,96.667 108.868,97.792 108.868,98.142 108.993,98.267 109.318,98.267 109.493,98.442 109.493,98.717 109.393,98.817 109.018,98.817 108.868,98.967 108.868,99.192 109.043,99.367 109.393,99.367 109.493,99.467 109.493,99.742 109.293,99.942 U2.A2@108.468,99.942
DDR3_DQ14: U1.H1 U2.B8 | length 33
  Top Layer w0.152: U1.H1@99.798,77.512 99.798,79.96 100.351,80.512 100.351,84.587 103.801,88.037 103.801,88.412 103.551,88.662 103.551,88.937 103.701,89.087 103.901,89.087 104.226,88.762 104.551,88.762 104.651,88.862 104.651,89.062 103.776,89.937 103.776,90.137 103.976,90.337 104.151,90.337 105.026,89.462 105.276,89.462 105.426,89.612 105.426,89.887 104.476,90.837 104.476,90.987 104.651,91.162 104.876,91.162 105.776,90.262 106.026,90.262 106.176,90.412 106.176,90.612 105.526,91.262 105.526,91.862 105.876,92.212 106.426,92.212 106.601,92.037 106.601,91.637 106.776,91.462 107.051,91.462 107.151,91.562 107.151,92.012 107.351,92.212 107.526,92.212 107.676,92.062 107.676,91.587 107.801,91.462 108.051,91.462 108.201,91.612 108.201,92.087 108.301,92.187 v2(108.726,92.187) ; U2.B8@107.601,95.087 107.976,94.712 v2(108.001,94.712)
  Bottom Layer w0.152: v2(108.001,94.712) 108.051,94.712 108.451,94.312 108.451,93.562 108.776,93.237 v2@108.776,92.237
DDR3_DQ15: U1.J1 U2.A3 | length 32.9
  Top Layer w0.152: U1.J1@98.98,77.541 98.98,80.335 99.612,80.966 99.612,85.166 102.762,88.316 102.762,90.316 105.562,93.116 108.837,93.116 109.612,93.891 109.612,96.191 108.137,97.666 106.062,97.666 105.937,97.791 105.937,98.066 106.087,98.216 108.187,98.216 108.387,98.416 U2.A3@108.387,99.116
DDR3_DQS0_N: U1.B2 U2.G3 | length 32.6
  Top Layer w0.152: v2(103.343,98.567) 103.568,98.567 103.743,98.742 103.743,99.017 U2.G3@103.593,99.167 ; U1.B2@104.614,76.719 105.018,77.123 105.018,78.192 105.718,78.892 105.718,80.942 110.718,85.942 v2(111.068,85.942)
  Bottom Layer w0.152: v2(103.343,98.567) 103.568,98.567 103.918,98.917 104.693,98.917 106.068,97.542 109.668,97.542 111.543,95.667 111.543,86.767 111.118,86.342 v2@111.118,85.992
DDR3_DQS0_P: U1.C2 U2.F3 | length 32.7
  Top Layer w0.152: U1.C2@103.81,76.719 104.193,77.102 104.193,77.743 104.186,77.749 104.186,78.211 104.493,78.517 104.818,78.517 105.393,79.092 105.393,81.092 110.418,86.117 v2(110.418,86.592) ; v2(103.918,97.992) 103.918,98.292 104.293,98.667 104.293,99.067 U2.F3@104.393,99.167
  Bottom Layer w0.152: v2@103.918,98.067 103.918,98.342 104.168,98.592 104.568,98.592 105.968,97.192 109.493,97.192 111.218,95.467 111.218,86.842 110.968,86.592 v2(110.418,86.592)
DDR3_DQS1_N: U1.F2 U2.B7 | length 32.6
  Top Layer w0.152: U1.F2@101.398,76.719 101.018,77.099 101.018,78.942 102.068,79.992 102.068,82.692 103.668,84.292 104.393,84.292 104.818,84.717 104.818,85.242 104.343,85.717 104.343,85.942 104.543,86.142 104.793,86.142 105.468,85.467 105.943,85.467 106.293,85.817 106.293,86.317 105.568,87.042 105.568,87.317 105.693,87.442 105.893,87.442 106.593,86.742 107.093,86.742 107.443,87.092 107.443,87.542 106.918,88.067 106.918,88.567 107.018,88.667 107.418,88.667 107.693,88.392 108.143,88.392 108.593,88.842 v2@109.018,88.842 ; v2(107.218,96.342) 107.218,96.292 U2.B7@107.593,95.917
  Bottom Layer w0.152: v2(107.218,96.342) 106.993,96.117 106.993,95.917 107.343,95.567 109.043,95.567 109.593,95.017 109.593,89.817 109.093,89.317 v2@109.093,88.992
  other v2: 109.068,88.842
DDR3_DQS1_P: U1.G2 U2.C7 | length 32.9
  Top Layer w0.152: U1.G2@100.594,76.719 100.186,77.127 100.186,78.611 101.768,80.192 101.768,82.817 103.593,84.642 104.218,84.642 104.468,84.892 104.468,85.117 104.018,85.567 104.018,86.142 104.368,86.492 104.868,86.492 105.543,85.817 105.818,85.817 105.968,85.967 105.968,86.142 105.193,86.917 105.193,87.392 105.593,87.792 106.018,87.792 106.718,87.092 106.968,87.092 107.093,87.217 107.093,87.442 106.593,87.942 106.593,88.692 106.893,88.992 107.543,88.992 107.818,88.717 108.018,88.717 108.418,89.117 v2(108.418,89.467) ; v2(106.418,96.342) 106.418,96.292 U2.C7@106.793,95.917
  Bottom Layer w0.152: v2@106.493,96.292 106.693,96.092 106.693,95.767 107.243,95.217 108.918,95.217 109.268,94.867 109.268,89.942 108.793,89.467 v2(108.418,89.467)
DDR3_ODT: U1.N5 U2.K1 | length 43.3
  Top Layer w0.152: v2(90.295,94.086) 89.67,94.086 89.42,94.336 89.42,98.286 94.57,103.436 100.42,103.436 v5(101.245,102.611) 101.195,102.561 U2.K1@101.195,100.711 ; v2(95.403,74.676) 95.411,74.676 U1.N5@95.756,74.331
  Bottom Layer w0.152: v2@90.32,94.136 90.345,94.111 90.345,86.811 91.045,86.111 91.045,84.461 91.595,83.911 91.578,83.894 91.578,81.776 93.878,79.476 93.878,77.376 94.253,77.001 94.253,75.826 v2@95.428,74.651 ; v5@101.245,102.736 v5@101.295,102.686
DDR3_RAS: U1.P4 U2.J3 | length 42.3
  Top Layer w0.152: v2(92.614,78.633) 92.739,78.758 94.664,78.758 95.039,78.383 95.039,78.208 94.627,77.706 94.627,75.547 U1.P4@94.963,75.112 ; v2(93.765,95.091) 93.765,95.766 95.39,97.391 99.54,97.391 99.815,97.666 100.99,97.666 101.24,97.916 v2(101.24,98.516) 101.34,98.516 U2.J3@101.99,99.166
  Bottom Layer w0.152: v2@92.639,78.658 92.639,79.583 90.564,81.658 90.564,83.49 90.565,83.491 90.565,83.516 89.415,84.666 89.415,95.541 89.615,95.741 91.39,95.741 91.59,95.541 91.59,94.516 91.79,94.316 91.99,94.316 92.14,94.466 92.14,95.516 92.34,95.716 92.54,95.716 92.665,95.591 92.665,95.241 92.815,95.091 v2@93.665,95.091 ; v2@101.165,98.516 v2@101.24,98.441
DDR3_RESET: R1.1 U1.B4 U2.T2 | length 34.6
  Top Layer w0.152: v2(95.764,99.933) 96.364,99.933 U2.T2@96.389,99.958 ; v2(104.189,74.708) 104.207,74.708 U1.B4@104.611,75.112
  Bottom Layer w0.152: R1.1@95.352,101.36 95.352,100.346 v2(95.764,99.933) 96.614,99.083 99.914,99.083 102.414,96.583 102.414,94.983 102.783,94.615 102.783,91.29 103.289,90.783 103.289,87.983 103.664,87.608 103.664,79.508 105.114,78.058 105.114,77.233 103.808,75.927 103.808,75.015 104.114,74.708 v2(104.189,74.708)
DDR3_VREF: C1.1 R4.1 R5.2 U1.H6 U1.P6 U2.H1 U2.M8 | length 62.9
  Top Layer w0.305: v1@94.617,73.913 U1.P6@95.01,73.52 ; U2.M8@99.593,95.086 99.593,95.136 v2@99.968,95.511 ; U2.H1@102.794,100.711 v2(103.193,101.111)
  Top Layer w0.356: U1.H6@99.81,73.52 99.822,73.52 100.203,73.139 v1(100.229,73.139) ; v2(100.718,97.036) 102.043,97.036 v2(102.393,97.386)
  Bottom Layer w0.152: v1(94.61,73.913) 95.016,73.508 98.395,73.508 98.429,73.542 99.826,73.542 v1(100.229,73.139)
  Bottom Layer w0.203: 91.415,78.816 91.415,76.124 91.872,75.667 91.872,75.251 91.592,74.972 91.592,73.812 91.897,73.508 94.204,73.508 v1(94.61,73.913)
  Bottom Layer w0.305: 91.415,78.816 88.113,82.118 88.113,98.092 88.953,98.933 92.05,98.933 93.955,97.028 98.501,97.028 v2@100.018,95.511 ; v2(100.043,95.486) v2@100.018,95.511 ; v2@100.743,97.011 100.018,96.286 v2@100.018,95.511
  Bottom Layer w0.356: v2(102.393,97.386) 101.893,97.886 102.562,98.555 102.562,99.768 102.972,100.178 102.972,100.877 103.193,101.099 v2(103.193,101.111)
  Bottom Layer w0.508: v2(103.193,101.111) 103.418,101.336 R5.2@103.418,104.648
DDR3_WE: U1.M5 U2.L3 | length 40.4
  Top Layer w0.152: v2(90.94,90.041) 90.94,90.691 92.115,91.866 92.54,91.866 93.115,92.441 93.115,93.966 93.515,94.366 93.515,94.716 93.24,94.991 93.24,95.766 95.265,97.791 99.34,97.791 99.565,98.016 99.565,98.541 99.715,98.691 99.965,98.691 100.065,98.591 100.065,98.141 100.165,98.041 100.565,98.041 100.715,98.191 100.715,98.841 100.39,99.166 U2.L3@100.34,99.166 ; U1.M5@96.569,74.322 96.617,74.322 97.003,74.707 v2(97.003,74.752)
  Bottom Layer w0.152: v2@90.965,89.966 90.965,88.741 91.09,88.616 92.39,88.616 92.515,88.491 92.515,88.241 92.39,88.116 90.965,88.116 90.865,88.016 90.865,87.816 91.065,87.616 93.14,87.616 94.665,86.091 94.665,83.541 94.662,83.537 94.662,81.516 96.187,79.991 96.187,78.241 96.181,78.235 96.181,77.698 96.612,77.266 96.612,76.441 96.606,76.435 96.606,75.098 v2@96.937,74.766
EN_AGC: U1.W19 U5.G5 | length 13.8
  Top Layer w0.127: v1(89.44,59.468) 89.484,59.512 89.535,59.512 89.814,59.792 89.814,61.138 90.602,61.925 90.602,62.459 91.005,62.862 91.005,63.116 U1.W19@91.01,63.12 ; U5.G5@91.554,52.134 v1(91.954,51.734)
  Bottom Layer w0.127: v1(89.44,59.468) 89.453,59.481 89.559,59.481 90.754,58.286 90.754,53.309 91.913,52.15 91.913,51.776 v1(91.954,51.734)
ENABLE: U1.V15 U5.G6 | length 19.2
  Top Layer w0.127: U5.G6@91.554,52.934 91.541,52.934 91.161,53.315 91.161,58.115 90.64,58.636 89.721,58.636 89.482,58.875 89.029,58.875 87.122,60.782 87.122,63.779 89.205,65.862 91.352,65.862 U1.V15@91.81,66.32
ETH_MDC: U1.C10 U3.30 | length 39.7
  Top Layer w0.127: U1.C10@103.81,70.32 103.864,70.32 104.133,70.59 v1(104.187,70.59)
  Top Layer w0.203: v1(129.891,83.06) 129.938,83.108 130.29,83.108 130.976,83.793 U3.30@130.976,84.818
  Bottom Layer w0.102: v1(104.187,70.59) 105.22,70.59 105.626,70.184 105.908,69.903 108.288,69.903 108.897,69.293 108.897,68.752 109.729,67.92 115.502,67.92 116.365,68.783 116.365,71.163 119.879,74.676 124.689,74.676 126.34,76.327 126.34,79.679 128.505,81.844 128.675,81.844 v1(129.891,83.06)
ETH_MDIO: R34.2 U1.C11 U3.31 | length 41.5
  Top Layer w0.102: R34.2@128.931,82.068 128.956,82.068 129.515,81.51 v1(129.515,80.714)
  Top Layer w0.127: U1.C11@103.81,69.52 103.849,69.52 104.164,69.835 v1(104.203,69.835)
  Top Layer w0.203: R34.2@128.956,82.068 129.459,82.571 130.197,82.571 131.376,83.75 U3.31@131.376,84.818
  Bottom Layer w0.102: v1(104.203,69.835) 104.286,69.835 104.625,69.496 108.12,69.496 108.491,69.125 108.491,68.583 109.561,67.513 115.67,67.513 116.772,68.615 116.772,70.994 120.047,74.27 124.857,74.27 126.746,76.159 126.746,78.918 128.658,80.83 129.399,80.83 v1(129.515,80.714)
ETH_RXCK: U1.B17 U3.19 | length 44.2
  Top Layer w0.102: U1.B17@104.61,64.72 104.947,64.72 105.326,65.1 109.504,65.1 110.012,64.592 116.383,64.592 118.085,66.294 121.744,66.294 124.231,68.782 124.231,72.278 126.187,74.233 126.187,82.906 125.476,83.617 v1(125.477,84.151) v1(125.477,84.151)
  Top Layer w0.203: v1(126.786,86.904) 126.786,86.966 127.335,87.515 128.272,87.515 U3.19@128.276,87.518
  Bottom Layer w0.203: v1(125.477,84.151) 125.544,84.151 125.797,84.404 126.721,84.404 127.229,84.912 127.229,86.03 126.833,86.425 126.833,86.857 v1(126.786,86.904)
ETH_RXCTL: R36.2 U1.D13 U3.13 | length 54.8
  Top Layer w0.127: U1.D13@103.01,67.92 103.403,67.527 103.403,67.521 v1(103.407,67.517)
  Top Layer w0.203: R36.2@125.571,90.754 125.622,90.703 v1(126.644,90.703) 126.67,90.678 127.126,90.678 127.886,89.918 U3.13@128.276,89.918
  Bottom Layer w0.102: v1(103.407,67.517) 103.418,67.517 103.675,67.259 104.587,67.259 105.139,66.708 108.355,66.708 108.997,66.065 117.03,66.065 117.827,66.862 117.827,70.613 120.011,72.796 124.535,72.796 127.838,76.1 127.838,77.887 v1(128.009,78.057)
  Bottom Layer w0.203: v1@126.644,90.627 127.33,90.627 127.675,90.282 127.675,86.324 127.931,86.067 127.931,85.042 128.188,84.785 130.15,84.785 130.988,83.947 130.988,83.922 131.099,83.81 131.099,80.325 129.591,78.816 128.768,78.816 v1(128.009,78.057)
ETH_RXD0: R41.1 U1.D11 U3.14 | length 51.9
  Top Layer w0.127: U1.D11@103.01,69.52 v1@103.403,69.914
  Top Layer w0.203: R41.1@125.572,89.441 125.673,89.543 v1(127.247,89.543) ; v1@127.247,89.553 127.846,89.553 127.881,89.518 U3.14@128.276,89.518
  Bottom Layer w0.102: v1(103.403,69.918) 103.445,69.918 103.905,69.458 104.376,69.458 104.568,69.266 108.063,69.266 108.288,69.04 108.288,68.499 109.477,67.31 115.754,67.31 116.975,68.531 116.975,70.91 120.131,74.066 124.943,74.066 126.949,76.073 126.949,78.813 128.763,80.627 129.025,80.627 129.315,80.337 129.671,80.337 130.215,80.881 130.215,81.98 130.734,82.499 130.734,83.842 130.044,84.531 128.041,84.531 127.495,85.077 127.495,86.144 127.254,86.385 127.254,89.535 v1(127.247,89.543)
ETH_RXD1: R39.1 U1.A16 U3.16 | length 45.9
  Top Layer w0.102: U1.A16@105.41,65.52 109.371,65.52 110.096,64.795 116.299,64.795 118,66.497 121.66,66.497 124.028,68.866 124.028,72.362 125.984,74.318 125.984,82.245 124.855,83.374 v1(124.827,83.374)
  Top Layer w0.203: R39.1@125.572,88.298 125.64,88.367 v1(126.416,88.367) 126.492,88.367 126.8,88.675 128.233,88.675 U3.16@128.276,88.718
  Bottom Layer w0.203: v1(124.827,83.374) 124.827,83.402 124.235,83.994 124.235,86.971 125.63,88.367 v1(126.416,88.367)
ETH_RXD2: R43.1 U1.F15 U3.17 | length 63.2
  Top Layer w0.102: R43.1@125.572,87.13 R43.1@125.572,87.155
  Top Layer w0.127: U1.F15@101.41,66.32 101.416,66.32 101.805,65.931 v1(101.811,65.931)
  Top Layer w0.203: R43.1@125.572,87.155 125.75,87.333 126.043,87.333 127.028,88.318 U3.17@128.276,88.318
  Bottom Layer w0.102: v1(101.811,65.931) 101.811,65.924 102.185,65.55 102.785,65.55 103.006,65.771 103.006,66.06 103.093,66.146 103.114,66.146 103.317,66.35 103.564,66.35 103.802,66.588 103.802,66.759 104.1,67.056 104.503,67.056 105.054,66.504 108.271,66.504 108.913,65.862 117.114,65.862 118.03,66.778 118.03,70.529 120.095,72.593 124.619,72.593 128.067,76.041 128.067,77.546 129.083,78.562 129.819,78.562 131.394,80.137 131.394,83.9 130.255,85.039 128.549,85.039 128.321,85.268 128.321,86.182 128.041,86.462 128.041,90.678 127.406,91.313 126.517,91.313 126.162,90.957 126.162,90.094 127.047,89.208 127.047,88.452 v1(126.225,87.63)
